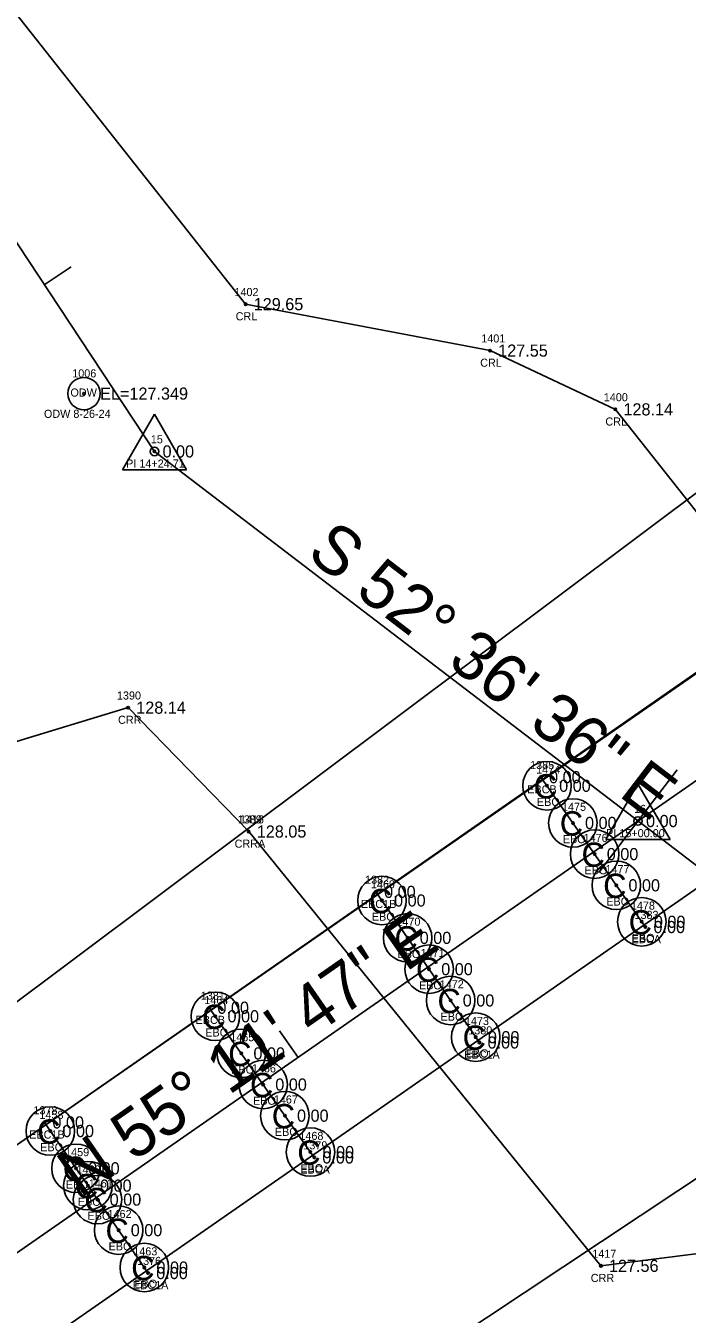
# Model space of a CAD drawing. Extents: x 2449052 to 2452984, y 1012343 to 1015262.
# Drawn here: x 2450986.4 to 2451068.2, y 1013885.3 to 1014044.7 of the extents above; entities that cross this region are included whole.
import ezdxf

# ---------------------------------------------------------------- set-up
doc = ezdxf.new("R2010")
doc.units = 0
for name, color, linetype in [('RD_EX_Bridge', 7, 'Continuous'), ('RD_EX_Bridge_txCode', 7, 'Continuous'), ('RD_EX_H2O', 7, 'Continuous'), ('RD_EX_H2O_txCode', 7, 'Continuous'), ('RD_EX_TX_Bridge_ELEV', 7, 'Continuous'), ('RD_EX_TX_H2O_ELEV', 7, 'Continuous'), ('RD_EX_UT', 7, 'Continuous'), ('RD_EX_VEG', 7, 'Continuous'), ('RD_HC_Cl', 7, 'Continuous'), ('RD_HC_Data', 7, 'Continuous'), ('RD_HC_Data_Tic', 7, 'Continuous'), ('RD_HC_Survey_ELEV', 7, 'Continuous'), ('RD_HC_txCode', 7, 'Continuous'), ('RD_SMD_Locator', 7, 'Continuous')]:
    doc.layers.add(name, color=color, linetype=linetype)

msp = doc.modelspace()

# ---------------------------------------------------------------- linework, layer by layer
at = {"layer": 'RD_EX_Bridge'}
for p, q in [((2450906.39, 1013851.41), (2451112.28, 1013994.58)), ((2451063.05, 1013933.22), (2451050.13, 1013951.75)), ((2451042.52, 1013918.94), (2451029.72, 1013937.57)), ((2451022.08, 1013904.72), (2451009.1, 1013923.24)), ((2451001.53, 1013890.43), (2450988.69, 1013909.06))]:
    msp.add_line(p, q, dxfattribs=at)
msp.add_lwpolyline([(2450906.39, 1013851.41), (2450918.83, 1013833.38), (2451124.8, 1013976.5), (2451112.28, 1013994.58)], dxfattribs=at)
for centre in [(2451050.88, 1013950.69), (2451054.08, 1013946.09), (2451056.77, 1013942.24), (2451059.45, 1013938.38), (2451030.46, 1013936.5), (2451062.6, 1013933.87), (2451033.63, 1013931.88), (2451036.29, 1013928.01), (2451038.95, 1013924.14), (2451009.85, 1013922.18), (2451042.06, 1013919.6), (2451013.06, 1013917.59), (2451015.76, 1013913.74), (2451018.45, 1013909.89), (2450989.43, 1013907.99), (2451021.61, 1013905.39), (2450992.6, 1013903.38), (2450994.08, 1013901.24), (2450995.27, 1013899.51), (2450997.88, 1013895.73), (2451001.06, 1013891.11)]:
    msp.add_circle(centre, 3, dxfattribs=at)
at = {"layer": 'RD_EX_H2O'}
for points in [[(2451076.27, 1013975.88), (2451059.33, 1013997.24), (2451043.84, 1014004.51), (2451013.59, 1014010.25), (2450971.36, 1014063.66), (2450950.38, 1014113.9), (2450903.35, 1014181.04), (2450858.87, 1014238.54), (2450803.46, 1014305.74), (2450763.02, 1014336.58)], [(2451013.97, 1013945.03), (2450999.06, 1013960.35), (2450947.69, 1013944.74), (2450914.65, 1013943.05), (2450847.57, 1013923.14)], [(2451013.97, 1013945.03), (2451057.54, 1013891.32), (2451091.48, 1013895.61), (2451128.22, 1013908.9), (2451192.3, 1013916.72), (2451258.16, 1013897.77), (2451360.62, 1013918.96), (2451380.18, 1013913.42), (2451411.99, 1013899.59), (2451448.35, 1013846.37), (2451473.38, 1013809.13)]]:
    msp.add_lwpolyline(points, dxfattribs=at)
for radius in [2, 0.15]:
    msp.add_circle((2450993.59, 1013999.19), radius, dxfattribs=at)
at = {"layer": 'RD_EX_UT'}
msp.add_line((2450907.79, 1013852.49), (2451110, 1013992.8), dxfattribs=at)
at = {"layer": 'RD_EX_VEG'}
for points in [[(2450511.25, 1013744.81), (2450612.22, 1013672.34), (2450883.9, 1013848.07), (2451091.43, 1014003.45), (2451271.45, 1014121.26), (2451583.45, 1014347.48), (2451819.08, 1014511.44), (2452219.54, 1014796.6), (2452332.78, 1014867.52)], [(2450813.9, 1013614.45), (2450759.99, 1013659.53), (2450819.72, 1013713.9), (2450939.16, 1013815.82), (2451225.29, 1014005.48), (2451628.56, 1014273.87), (2452372.22, 1014794.45)]]:
    msp.add_lwpolyline(points, dxfattribs=at)
at = {"layer": 'RD_HC_Cl'}
for p, q in [((2449680.91, 1012986.23), (2452350.19, 1014841.68)), ((2450869.17, 1014193.49), (2451002.31, 1013992.04)), ((2451002.31, 1013992.04), (2451086.18, 1013927.94))]:
    msp.add_line(p, q, dxfattribs=at)
at = {"layer": 'RD_HC_Data'}
for p, q in [((2450998.34, 1013989.75), (2451002.31, 1013996.63)), ((2451002.31, 1013996.63), (2451006.28, 1013989.75)), ((2450998.34, 1013989.75), (2451006.28, 1013989.75)), ((2451058.15, 1013944.03), (2451062.13, 1013950.91)), ((2451062.13, 1013950.91), (2451066.1, 1013944.03)), ((2451058.15, 1013944.03), (2451066.1, 1013944.03))]:
    msp.add_line(p, q, dxfattribs=at)
for centre in [(2451002.31, 1013992.04), (2451062.13, 1013946.33)]:
    msp.add_circle(centre, 0.529, dxfattribs=at)
at = {"layer": 'RD_HC_Data_Tic'}
for p, q in [((2450988.68, 1014012.66), (2450992.02, 1014014.87)), ((2451062.13, 1013946.33), (2451066.98, 1013952.68)), ((2451062.13, 1013946.33), (2451057.27, 1013939.97)), ((2451020.08, 1013917.1), (2451017.8, 1013920.39))]:
    msp.add_line(p, q, dxfattribs=at)
at = {"layer": 'RD_SMD_Locator'}
for centre in [(2451013.59, 1014010.25), (2451043.84, 1014004.51), (2451059.33, 1013997.24), (2451002.31, 1013992.04), (2450999.06, 1013960.35), (2451050.13, 1013951.75), (2451050.88, 1013950.69), (2451054.08, 1013946.09), (2451062.13, 1013946.33), (2451013.97, 1013945.03), (2451013.97, 1013945.03), (2451056.77, 1013942.24), (2451029.72, 1013937.57), (2451059.45, 1013938.38), (2451030.46, 1013936.5), (2451062.6, 1013933.87), (2451063.05, 1013933.22), (2451033.63, 1013931.88), (2451036.29, 1013928.01), (2451009.1, 1013923.24), (2451038.95, 1013924.14), (2451009.85, 1013922.18), (2451042.06, 1013919.6), (2451042.52, 1013918.94), (2451013.06, 1013917.59), (2451015.76, 1013913.74), (2450988.69, 1013909.06), (2451018.45, 1013909.89), (2450989.43, 1013907.99), (2451021.61, 1013905.39), (2451022.08, 1013904.72), (2450992.6, 1013903.38), (2450994.08, 1013901.24), (2450995.27, 1013899.51), (2450997.88, 1013895.73), (2451057.54, 1013891.32), (2451001.06, 1013891.11), (2451001.53, 1013890.43)]:
    msp.add_circle(centre, 0.15, dxfattribs=at)

# ---------------------------------------------------------------- texts
at = {"layer": 'RD_EX_Bridge'}
for p in [(2451049.24, 1013949.12), (2451052.45, 1013944.53), (2451055.14, 1013940.67), (2451057.82, 1013936.82), (2451028.83, 1013934.94), (2451060.97, 1013932.31), (2451032, 1013930.32), (2451034.66, 1013926.45), (2451037.32, 1013922.57), (2451008.21, 1013920.62), (2451040.43, 1013918.04), (2451011.43, 1013916.03), (2451014.13, 1013912.18), (2451016.82, 1013908.33), (2450987.8, 1013906.43), (2451019.98, 1013903.83), (2450990.97, 1013901.82), (2450992.45, 1013899.68), (2450993.64, 1013897.95), (2450996.25, 1013894.16), (2450999.43, 1013889.55)]:
    msp.add_text('C', height=3, dxfattribs=at).set_placement(p)
at = {"layer": 'RD_EX_Bridge_txCode'}
for s, p in [('1385', (2451048.79, 1013952.75)), ('1474', (2451049.53, 1013952.19)), ('EBCB', (2451048.43, 1013949.75)), ('EBO', (2451049.63, 1013948.19)), ('1475', (2451052.73, 1013947.59)), ('EBO', (2451052.83, 1013943.59)), ('1476', (2451055.4, 1013943.74)), ('1477', (2451058.11, 1013939.88)), ('1382', (2451028.37, 1013938.57)), ('EBO', (2451055.52, 1013939.74)), ('1469', (2451029.09, 1013938)), ('EBC1B', (2451027.85, 1013935.57)), ('EBO', (2451058.21, 1013935.88)), ('1478', (2451061.25, 1013935.37)), ('EBO', (2451029.21, 1013934)), ('1470', (2451032.24, 1013933.38)), ('1383', (2451061.7, 1013934.22)), ('EBCA', (2451061.33, 1013931.22)), ('EBO', (2451061.36, 1013931.37)), ('EBO', (2451032.38, 1013929.38)), ('1471', (2451035.23, 1013929.51)), ('EBO', (2451035.04, 1013925.51)), ('1472', (2451037.6, 1013925.64)), ('1381', (2451008.04, 1013924.24)), ('1464', (2451008.48, 1013923.68)), ('EBCB', (2451007.4, 1013921.24)), ('EBO', (2451037.71, 1013921.64)), ('1473', (2451040.72, 1013921.1)), ('EBO', (2451008.6, 1013919.68)), ('1465', (2451011.69, 1013919.09)), ('1380', (2451041.13, 1013919.94)), ('EBC1A', (2451040.64, 1013916.94)), ('EBO', (2451040.82, 1013917.1)), ('EBO', (2451011.81, 1013915.09)), ('1466', (2451014.36, 1013915.24)), ('EBO', (2451014.51, 1013911.24)), ('1467', (2451017.08, 1013911.39)), ('1378', (2450987.34, 1013910.06)), ('1458', (2450988.08, 1013909.49)), ('EBC1B', (2450986.82, 1013907.06)), ('EBO', (2451017.21, 1013907.39)), ('1468', (2451020.24, 1013906.89)), ('EBO', (2450988.18, 1013905.49)), ('1459', (2450991.26, 1013904.88)), ('1379', (2451020.73, 1013905.72)), ('1460', (2450992.67, 1013902.74)), ('EBO', (2451020.36, 1013902.89)), ('EBCA', (2451020.36, 1013902.72)), ('EBO', (2450991.36, 1013900.88)), ('1461', (2450994.19, 1013901.01)), ('EBO', (2450992.84, 1013898.74)), ('EBO', (2450994.03, 1013897.01)), ('1462', (2450996.51, 1013897.23)), ('EBO', (2450996.64, 1013893.23)), ('1463', (2450999.69, 1013892.61)), ('1376', (2451000.16, 1013891.43)), ('EBC1A', (2450999.65, 1013888.43)), ('EBO', (2450999.82, 1013888.61))]:
    msp.add_text(s, height=1, dxfattribs=at).set_placement(p)
at = {"layer": 'RD_EX_H2O'}
msp.add_text('ODW', height=1, dxfattribs=at).set_placement((2450991.92, 1013998.82))
at = {"layer": 'RD_EX_H2O_txCode'}
for s, p in [('1402', (2451012.21, 1014011.25)), ('CRL', (2451012.36, 1014008.25)), ('1401', (2451042.74, 1014005.51)), ('CRL', (2451042.61, 1014002.51)), ('1006', (2450992.14, 1014001.19)), ('1400', (2451057.9, 1013998.24)), ('ODW 8-26-24', (2450988.64, 1013996.19)), ('CRL', (2451058.1, 1013995.24)), ('1390', (2450997.67, 1013961.35)), ('CRR', (2450997.81, 1013958.35)), ('1389', (2451012.62, 1013946.03)), ('1416', (2451012.88, 1013946.03)), ('CRRA', (2451012.23, 1013943.03)), ('CRRA', (2451012.23, 1013943.03)), ('1417', (2451056.48, 1013892.32)), ('CRR', (2451056.29, 1013889.32))]:
    msp.add_text(s, height=1, dxfattribs=at).set_placement(p)
at = {"layer": 'RD_EX_TX_Bridge_ELEV'}
for p in [(2451051.13, 1013951), (2451052.38, 1013949.94), (2451055.58, 1013945.34), (2451058.27, 1013941.49), (2451030.72, 1013936.82), (2451060.95, 1013937.63), (2451031.96, 1013935.75), (2451064.1, 1013933.12), (2451064.05, 1013932.47), (2451035.13, 1013931.13), (2451037.79, 1013927.26), (2451040.45, 1013923.39), (2451010.1, 1013922.49), (2451011.35, 1013921.43), (2451043.56, 1013918.85), (2451043.52, 1013918.19), (2451014.56, 1013916.84), (2451017.26, 1013912.99), (2451019.95, 1013909.14), (2450989.69, 1013908.31), (2450990.93, 1013907.24), (2451023.11, 1013904.64), (2450994.1, 1013902.63), (2451023.08, 1013903.97), (2450995.58, 1013900.49), (2450996.77, 1013898.76), (2450999.38, 1013894.98), (2451002.56, 1013890.36), (2451002.53, 1013889.68)]:
    msp.add_text('0.00', height=1.5, dxfattribs=at).set_placement(p)
at = {"layer": 'RD_EX_TX_H2O_ELEV'}
for s, p in [('129.65', (2451014.59, 1014009.5)), ('127.55', (2451044.84, 1014003.76)), ('EL=127.349', (2450995.59, 1013998.44)), ('128.14', (2451060.33, 1013996.49)), ('128.14', (2451000.06, 1013959.6)), ('128.05', (2451014.97, 1013944.28)), ('128.05', (2451014.97, 1013944.28)), ('127.56', (2451058.54, 1013890.57))]:
    msp.add_text(s, height=1.5, dxfattribs=at).set_placement(p)
at = {"layer": 'RD_HC_Data'}
for s, rotation, p in [('S 52%%d 36\' 36" E', 322.61, (2451020.96, 1013979.05)), ('N 55%%d 11\' 47" E', 34.8036, (2450993.12, 1013899.58))]:
    msp.add_text(s, height=6, rotation=rotation, dxfattribs=at).set_placement(p)
at = {"layer": 'RD_HC_Survey_ELEV'}
for p in [(2451003.31, 1013991.29), (2451063.13, 1013945.58)]:
    msp.add_text('0.00', height=1.5, dxfattribs=at).set_placement(p)
at = {"layer": 'RD_HC_txCode'}
for s, p in [('15', (2451001.86, 1013993.04)), ('PI 14+24.71', (2450998.81, 1013990.04)), ('16', (2451061.65, 1013947.33)), ('PI 15+00.00', (2451058.19, 1013944.33))]:
    msp.add_text(s, height=1, dxfattribs=at).set_placement(p)

doc.saveas('drawing.dxf')
